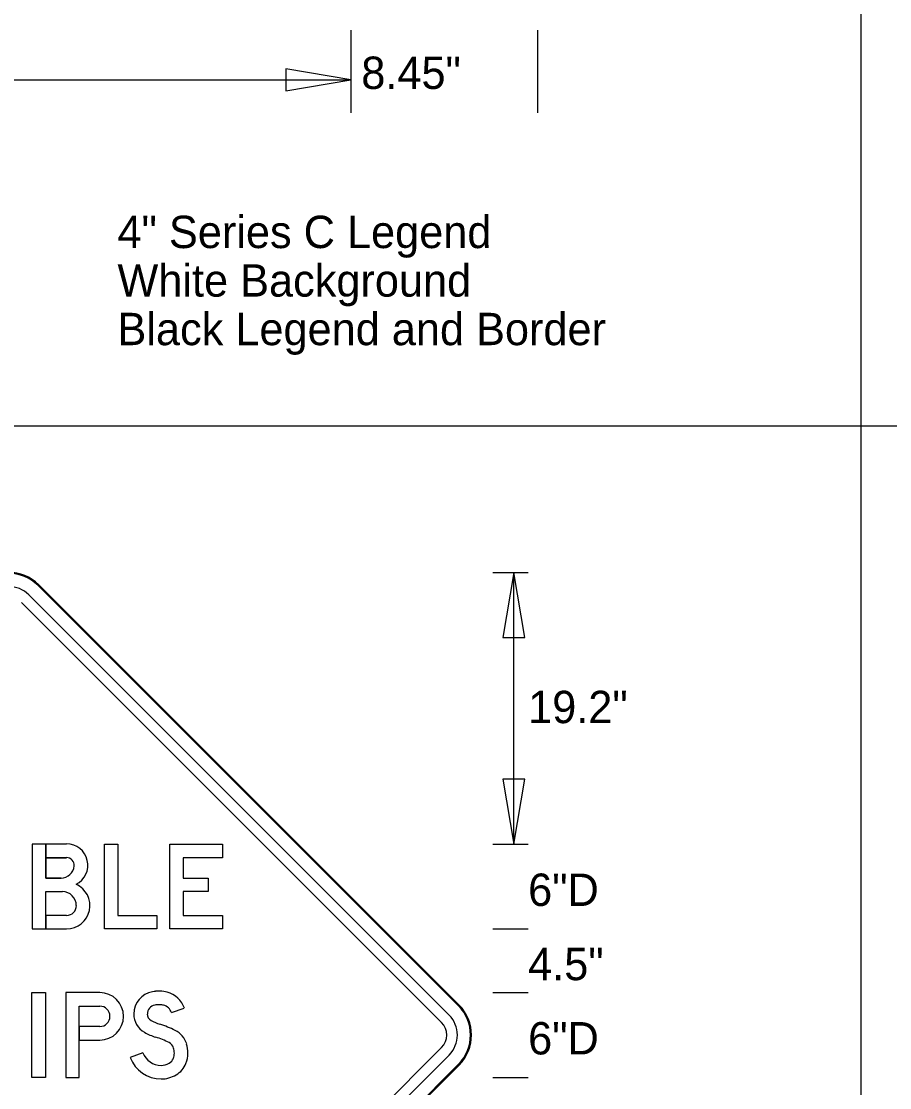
# Model space of a CAD drawing. Extents: x 0 to 770, y 0 to 495.
# Drawn here: x 486.7 to 580.6, y 93.4 to 208.7 of the extents above; entities that cross this region are included whole.
import ezdxf

# ---------------------------------------------------------------- set-up
doc = ezdxf.new("R2010")
doc.units = 0
for name, color, linetype in [('Dimension', 7, 'Continuous'), ('GSBWFill', 7, 'Continuous'), ('GSColorFill', 7, 'Continuous'), ('GSDims', 7, 'Continuous'), ('GSOutline', 7, 'Continuous'), ('SheetLines_dp', 7, 'Continuous'), ('TextStructures', 7, 'Continuous')]:
    doc.layers.add(name, color=color, linetype=linetype)

msp = doc.modelspace()

# ---------------------------------------------------------------- linework, layer by layer
at = {"layer": 'Dimension'}
for points in [[(522.3, 202.41), (515.29, 203.6), (515.29, 201.22)], [(539.95, 149.13), (538.76, 142.11), (541.14, 142.11)], [(539.95, 119.75), (541.14, 126.77), (538.76, 126.77)]]:
    msp.add_lwpolyline(points, close=True, dxfattribs=at)
at = {"layer": 'GSBWFill'}
for p, q in [((534.02, 102.34), (488.58, 147.78)), ((532.94, 101.26), (487.5, 146.7)), ((486.69, 145.89), (532.13, 100.45)), ((489.33, 114.61), (491.12, 114.61)), ((492.95, 102.22), (495.16, 102.22)), ((532.13, 97.74), (486.69, 52.31)), ((487.5, 51.5), (532.94, 96.93)), ((488.58, 50.41), (534.02, 95.85))]:
    msp.add_line(p, q, dxfattribs=at)
for points in [[(490.98, 116.08), (489.33, 116.08), (489.33, 119.75), (487.86, 119.75), (487.86, 110.57), (489.33, 110.57), (489.33, 114.61)], [(491.58, 119.75), (489.33, 119.75), (489.33, 118.28), (491.58, 118.28)], [(491.58, 112.04), (489.33, 112.04), (489.33, 110.57), (491.58, 110.57)], [(495.16, 103.69), (491.48, 103.69), (491.48, 94.51), (492.95, 94.51), (492.95, 102.22)], [(502.91, 101.52), (504.3, 101.99)], [(495.16, 100.01), (492.95, 100.01), (492.95, 98.55), (495.16, 98.55)], [(499.83, 97.18), (498.46, 96.66)]]:
    msp.add_lwpolyline(points, dxfattribs=at)
for points in [[(497.13, 112.04), (501.35, 112.04), (501.35, 110.57), (495.66, 110.57), (495.66, 119.75), (497.13, 119.75)], [(508.42, 118.28), (504.2, 118.28), (504.2, 116.08), (506.87, 116.08), (506.87, 114.61), (504.2, 114.61), (504.2, 112.04), (508.42, 112.04), (508.42, 110.57), (502.73, 110.57), (502.73, 119.75), (508.42, 119.75)], [(487.81, 103.69), (489.28, 103.69), (489.28, 94.51), (487.81, 94.51)]]:
    msp.add_lwpolyline(points, close=True, dxfattribs=at)
for centre, radius, start, end in [((485.33, 144.54), 4.59, 45, 135), ((485.33, 144.54), 3.06, 45, 135), ((491.58, 117.46), 2.3, 296.5254, 90), ((491.58, 117.46), 0.826, 355.5883, 90), ((490.98, 117.5), 1.42, 270, 355.5883), ((491.58, 113.1), 2.52, 270, 66.0465), ((491.12, 113.1), 1.51, 0, 90), ((491.58, 113.1), 1.06, 270, 0), ((530.77, 99.1), 4.59, 315, 45), ((530.77, 99.1), 1.91, 315, 45), ((530.77, 99.1), 3.06, 315, 45)]:
    msp.add_arc(centre, radius, start, end, dxfattribs=at)
for centre, major_axis, start_param, end_param in [((501.56, 99.86), (0, 3.98), 0.090794, 0.175685), ((501.68, 98.51), (0, 5.34), 6.283185, 6.373979), ((501.68, 100.92), (0, 2.92), 6.012094, 6.283185), ((495.16, 101.12), (0, 2.57), 3.141593, 6.283185), ((501.29, 101.37), (0, 2.45), 0.175685, 1.570796), ((501.74, 101.13), (0, 2.71), 5.034126, 6.012094), ((495.16, 101.12), (0, 1.1), 3.141593, 6.283185), ((501.29, 101.37), (0, 0.977), 0.175685, 1.570796), ((501.56, 99.86), (0, 2.51), 0.090794, 0.175685), ((501.68, 98.51), (0, 3.87), 0, 0.090794), ((501.68, 100.92), (0, 1.45), 6.012094, 6.283185), ((501.74, 101.13), (0, 1.24), 5.034126, 6.012094), ((501.1, 101.37), (0, 2.26), 1.570796, 2.627164), ((501.1, 101.37), (0, 0.794), 1.570796, 2.627164), ((503.18, 105.04), (0, 5.01), 2.627164, 2.834816), ((503.18, 105.04), (0, 6.48), 2.627164, 2.834816), ((498.22, 89.4), (0, 11.4), 5.820582, 5.976409), ((502.22, 97.41), (0, 2.45), 5.010707, 5.820582), ((498.22, 89.4), (0, 9.93), 5.820582, 5.976409), ((502.22, 97.41), (0, 0.978), 5.010707, 5.820582), ((501.38, 97.15), (0, 3.32), 4.712389, 5.010707), ((501.8, 97.92), (0, 2.1), 1.931277, 3.141593), ((501.67, 97.15), (0, 1.56), 4.331279, 4.712389), ((501.38, 97.15), (0, 1.85), 4.712389, 5.010707), ((501.67, 97.15), (0, 3.03), 4.331279, 4.712389), ((501.8, 97.92), (0, 3.57), 1.931277, 3.141593), ((501.8, 97.54), (0, 1.72), 3.141593, 3.672524), ((502.14, 96.97), (0, 1.06), 3.672524, 4.331279), ((502.14, 96.97), (0, 2.53), 3.672524, 4.331279), ((501.8, 97.54), (0, 3.19), 3.141593, 3.672524)]:
    msp.add_ellipse(centre, major_axis=major_axis, ratio=0.999993, start_param=start_param, end_param=end_param, dxfattribs=at)
at = {"layer": 'GSColorFill'}
for p, q in [((488.5, 147.7), (533.94, 102.26)), ((534.02, 102.34), (488.58, 147.78)), ((534.02, 102.34), (488.58, 147.78)), ((532.94, 101.26), (487.5, 146.7)), ((486.69, 145.89), (532.13, 100.45)), ((489.33, 114.61), (491.12, 114.61)), ((492.95, 102.22), (495.16, 102.22)), ((532.13, 97.74), (486.69, 52.31)), ((487.5, 51.5), (532.94, 96.93)), ((533.94, 95.93), (488.5, 50.49)), ((488.58, 50.41), (534.02, 95.85)), ((488.58, 50.41), (534.02, 95.85))]:
    msp.add_line(p, q, dxfattribs=at)
for points in [[(490.98, 116.08), (489.33, 116.08), (489.33, 119.75), (487.86, 119.75), (487.86, 110.57), (489.33, 110.57), (489.33, 114.61)], [(491.58, 119.75), (489.33, 119.75), (489.33, 118.28), (491.58, 118.28)], [(491.58, 112.04), (489.33, 112.04), (489.33, 110.57), (491.58, 110.57)], [(495.16, 103.69), (491.48, 103.69), (491.48, 94.51), (492.95, 94.51), (492.95, 102.22)], [(502.91, 101.52), (504.3, 101.99)], [(495.16, 100.01), (492.95, 100.01), (492.95, 98.55), (495.16, 98.55)], [(499.83, 97.18), (498.46, 96.66)]]:
    msp.add_lwpolyline(points, dxfattribs=at)
for points in [[(497.13, 112.04), (501.35, 112.04), (501.35, 110.57), (495.66, 110.57), (495.66, 119.75), (497.13, 119.75)], [(508.42, 118.28), (504.2, 118.28), (504.2, 116.08), (506.87, 116.08), (506.87, 114.61), (504.2, 114.61), (504.2, 112.04), (508.42, 112.04), (508.42, 110.57), (502.73, 110.57), (502.73, 119.75), (508.42, 119.75)], [(487.81, 103.69), (489.28, 103.69), (489.28, 94.51), (487.81, 94.51)]]:
    msp.add_lwpolyline(points, close=True, dxfattribs=at)
for centre, radius, start, end in [((485.33, 144.54), 4.59, 45, 135), ((485.33, 144.54), 4.59, 45, 135), ((485.33, 144.54), 4.48, 45, 135), ((485.33, 144.54), 3.06, 45, 135), ((491.58, 117.46), 2.3, 296.5254, 90), ((491.58, 117.46), 0.826, 355.5883, 90), ((490.98, 117.5), 1.42, 270, 355.5883), ((491.58, 113.1), 2.52, 270, 66.0465), ((491.12, 113.1), 1.51, 0, 90), ((491.58, 113.1), 1.06, 270, 0), ((530.77, 99.1), 4.48, 315, 45), ((530.77, 99.1), 4.59, 315, 45), ((530.77, 99.1), 4.59, 315, 45), ((530.77, 99.1), 1.91, 315, 45), ((530.77, 99.1), 3.06, 315, 45)]:
    msp.add_arc(centre, radius, start, end, dxfattribs=at)
for centre, major_axis, start_param, end_param in [((501.56, 99.86), (0, 3.98), 0.090794, 0.175685), ((501.68, 98.51), (0, 5.34), 6.283185, 6.373979), ((501.68, 100.92), (0, 2.92), 6.012094, 6.283185), ((495.16, 101.12), (0, 2.57), 3.141593, 6.283185), ((501.29, 101.37), (0, 2.45), 0.175685, 1.570796), ((501.74, 101.13), (0, 2.71), 5.034126, 6.012094), ((495.16, 101.12), (0, 1.1), 3.141593, 6.283185), ((501.29, 101.37), (0, 0.977), 0.175685, 1.570796), ((501.56, 99.86), (0, 2.51), 0.090794, 0.175685), ((501.68, 98.51), (0, 3.87), 0, 0.090794), ((501.68, 100.92), (0, 1.45), 6.012094, 6.283185), ((501.74, 101.13), (0, 1.24), 5.034126, 6.012094), ((501.1, 101.37), (0, 2.26), 1.570796, 2.627164), ((501.1, 101.37), (0, 0.794), 1.570796, 2.627164), ((503.18, 105.04), (0, 5.01), 2.627164, 2.834816), ((503.18, 105.04), (0, 6.48), 2.627164, 2.834816), ((498.22, 89.4), (0, 11.4), 5.820582, 5.976409), ((502.22, 97.41), (0, 2.45), 5.010707, 5.820582), ((498.22, 89.4), (0, 9.93), 5.820582, 5.976409), ((502.22, 97.41), (0, 0.978), 5.010707, 5.820582), ((501.38, 97.15), (0, 3.32), 4.712389, 5.010707), ((501.8, 97.92), (0, 2.1), 1.931277, 3.141593), ((501.67, 97.15), (0, 1.56), 4.331279, 4.712389), ((501.38, 97.15), (0, 1.85), 4.712389, 5.010707), ((501.67, 97.15), (0, 3.03), 4.331279, 4.712389), ((501.8, 97.92), (0, 3.57), 1.931277, 3.141593), ((501.8, 97.54), (0, 1.72), 3.141593, 3.672524), ((502.14, 96.97), (0, 1.06), 3.672524, 4.331279), ((502.14, 96.97), (0, 2.53), 3.672524, 4.331279), ((501.8, 97.54), (0, 3.19), 3.141593, 3.672524)]:
    msp.add_ellipse(centre, major_axis=major_axis, ratio=0.999993, start_param=start_param, end_param=end_param, dxfattribs=at)
at = {"layer": 'GSDims'}
for p, q in [((522.3, 207.78), (522.3, 198.83)), ((522.3, 207.78), (522.3, 198.83)), ((542.51, 207.78), (542.51, 198.83)), ((433.76, 202.41), (522.3, 202.41)), ((537.66, 149.13), (541.48, 149.13)), ((539.95, 119.75), (539.95, 149.13)), ((537.66, 119.75), (541.48, 119.75)), ((537.66, 119.75), (541.48, 119.75)), ((537.66, 110.57), (541.48, 110.57)), ((537.66, 110.57), (541.48, 110.57)), ((537.66, 103.69), (541.48, 103.69)), ((537.66, 103.69), (541.48, 103.69)), ((537.66, 94.51), (541.48, 94.51)), ((537.66, 94.51), (541.48, 94.51))]:
    msp.add_line(p, q, dxfattribs=at)
at = {"layer": 'GSOutline'}
for p, q in [((534.02, 102.34), (488.58, 147.78)), ((532.94, 101.26), (487.5, 146.7)), ((532.13, 100.45), (486.69, 145.89)), ((491.58, 118.28), (489.33, 118.28)), ((489.33, 114.61), (491.12, 114.61)), ((487.86, 110.57), (491.58, 110.57)), ((492.95, 98.55), (495.16, 98.55)), ((486.69, 52.3), (532.13, 97.74)), ((487.5, 51.49), (532.94, 96.93)), ((488.58, 50.41), (534.02, 95.85))]:
    msp.add_line(p, q, dxfattribs=at)
for points in [[(491.58, 119.75), (487.86, 119.75), (487.86, 110.57)], [(489.33, 118.28), (489.33, 116.08), (490.98, 116.08)], [(491.58, 112.04), (489.33, 112.04), (489.33, 114.61)], [(495.16, 103.69), (491.48, 103.69), (491.48, 94.51), (492.95, 94.51), (492.95, 98.55)], [(495.16, 100.01), (492.95, 100.01), (492.95, 102.22), (495.16, 102.22)], [(502.91, 101.52), (504.3, 101.99)], [(499.83, 97.18), (498.46, 96.66)]]:
    msp.add_lwpolyline(points, dxfattribs=at)
for points in [[(497.13, 112.04), (501.35, 112.04), (501.35, 110.57), (495.66, 110.57), (495.66, 119.75), (497.13, 119.75)], [(508.42, 118.28), (504.2, 118.28), (504.2, 116.08), (506.87, 116.08), (506.87, 114.61), (504.2, 114.61), (504.2, 112.04), (508.42, 112.04), (508.42, 110.57), (502.73, 110.57), (502.73, 119.75), (508.42, 119.75)], [(487.81, 103.69), (489.28, 103.69), (489.28, 94.51), (487.81, 94.51)]]:
    msp.add_lwpolyline(points, close=True, dxfattribs=at)
for centre, radius, start, end in [((485.33, 144.54), 4.59, 45, 135), ((485.33, 144.54), 3.06, 45, 135), ((491.58, 117.46), 2.3, 296.5254, 90), ((491.58, 117.46), 0.826, 355.5883, 90), ((490.98, 117.5), 1.42, 270, 355.5883), ((491.58, 113.1), 2.52, 270, 66.0465), ((491.12, 113.1), 1.51, 0, 90), ((491.58, 113.1), 1.06, 270, 0), ((530.77, 99.1), 4.59, 315, 45), ((530.77, 99.1), 1.91, 315, 45), ((530.77, 99.1), 3.06, 315, 45)]:
    msp.add_arc(centre, radius, start, end, dxfattribs=at)
for centre, major_axis, start_param, end_param in [((501.56, 99.86), (0, 3.98), 0.090794, 0.175685), ((501.68, 98.51), (0, 5.34), 6.283185, 6.373979), ((501.68, 100.92), (0, 2.92), 6.012094, 6.283185), ((495.16, 101.12), (0, 2.57), 3.141593, 6.283185), ((501.29, 101.37), (0, 2.45), 0.175685, 1.570796), ((501.74, 101.13), (0, 2.71), 5.034126, 6.012094), ((495.16, 101.12), (0, 1.1), 3.141593, 6.283185), ((501.29, 101.37), (0, 0.977), 0.175685, 1.570796), ((501.56, 99.86), (0, 2.51), 0.090794, 0.175685), ((501.68, 98.51), (0, 3.87), 0, 0.090794), ((501.68, 100.92), (0, 1.45), 6.012094, 6.283185), ((501.74, 101.13), (0, 1.24), 5.034126, 6.012094), ((501.1, 101.37), (0, 2.26), 1.570796, 2.627164), ((501.1, 101.37), (0, 0.794), 1.570796, 2.627164), ((503.18, 105.04), (0, 5.01), 2.627164, 2.834816), ((503.18, 105.04), (0, 6.48), 2.627164, 2.834816), ((498.22, 89.4), (0, 11.4), 5.820582, 5.976409), ((502.22, 97.41), (0, 2.45), 5.010707, 5.820582), ((498.22, 89.4), (0, 9.93), 5.820582, 5.976409), ((502.22, 97.41), (0, 0.978), 5.010707, 5.820582), ((501.38, 97.15), (0, 3.32), 4.712389, 5.010707), ((501.8, 97.92), (0, 2.1), 1.931277, 3.141593), ((501.67, 97.15), (0, 1.56), 4.331279, 4.712389), ((501.38, 97.15), (0, 1.85), 4.712389, 5.010707), ((501.67, 97.15), (0, 3.03), 4.331279, 4.712389), ((501.8, 97.92), (0, 3.57), 1.931277, 3.141593), ((501.8, 97.54), (0, 1.72), 3.141593, 3.672524), ((502.14, 96.97), (0, 1.06), 3.672524, 4.331279), ((502.14, 96.97), (0, 2.53), 3.672524, 4.331279), ((501.8, 97.54), (0, 3.19), 3.141593, 3.672524)]:
    msp.add_ellipse(centre, major_axis=major_axis, ratio=0.999993, start_param=start_param, end_param=end_param, dxfattribs=at)
at = {"layer": 'SheetLines_dp'}
for p, q in [((577.5, 0), (577.5, 495)), ((0, 165), (770, 165))]:
    msp.add_line(p, q, dxfattribs=at)

# ---------------------------------------------------------------- texts
at = {"layer": 'GSDims'}
for s, p in [('19.2"', (541.48, 132.83)), ('6"D', (541.48, 113.06)), ('4.5"', (541.48, 105.03)), ('6"D', (541.48, 97))]:
    msp.add_text(s, height=3.5, dxfattribs=at).set_placement(p)
at = {"layer": 'TextStructures'}
for s, p in [('8.45"', (523.44, 201.42)), ('4" Series C Legend', (497.08, 184.21)), ('White Background', (497.08, 178.96)), ('Black Legend and Border  ', (497.08, 173.71))]:
    msp.add_text(s, height=3.5, dxfattribs=at).set_placement(p)

doc.saveas('drawing.dxf')
